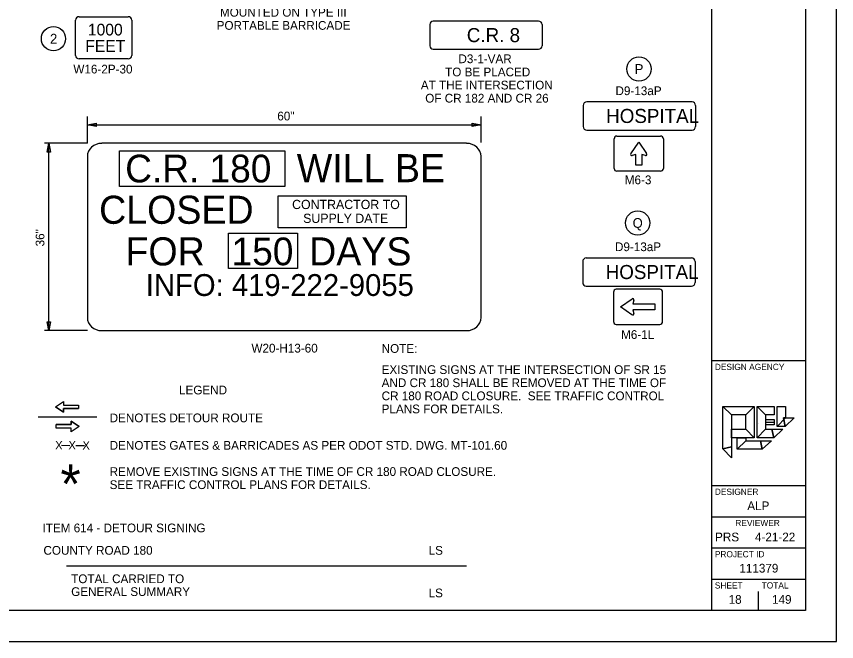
# Model space of a CAD drawing. Extents: x 1 to 1971, y -2 to 1107.
# Drawn here: x 1672.33 to 1685.46, y 1084.6 to 1094.62 of the extents above; entities that cross this region are included whole.
import ezdxf

# ---------------------------------------------------------------- set-up
doc = ezdxf.new("R2010")
doc.units = 0
for name, color, linetype in [('SH_Border', 7, 'Continuous'), ('SH_Cut_Line', 7, 'Continuous'), ('SH_Data', 7, 'Continuous'), ('SH_Text', 7, 'Continuous'), ('SN_P_Signs', 7, 'Continuous'), ('SN_P_Text', 7, 'Continuous')]:
    doc.layers.add(name, color=color, linetype=linetype)

msp = doc.modelspace()

# ---------------------------------------------------------------- linework, layer by layer
at = {"layer": 'SH_Border'}
for p, q in [((1683.463, 1085.101), (1683.463, 1106.101)), ((1683.463, 1089.101), (1684.963, 1089.101)), ((1683.463, 1087.101), (1684.963, 1087.101)), ((1683.463, 1086.601), (1684.963, 1086.601)), ((1683.463, 1086.101), (1684.963, 1086.101)), ((1683.463, 1085.601), (1684.963, 1085.601))]:
    msp.add_line(p, q, dxfattribs=at)
msp.add_lwpolyline([(1652.963, 1106.101), (1684.963, 1106.101), (1684.963, 1085.101), (1652.963, 1085.101)], close=True, dxfattribs=at)
at = {"layer": 'SH_Cut_Line'}
msp.add_lwpolyline([(1651.463, 1084.601), (1685.463, 1084.601), (1685.463, 1106.601), (1651.463, 1106.601)], close=True, dxfattribs=at)
at = {"layer": 'SH_Data'}
for p, q in [((1684.213, 1088.101), (1684.213, 1088.101)), ((1684.213, 1085.101), (1684.213, 1085.401)), ((1683.838, 1085.276), (1683.838, 1085.276))]:
    msp.add_line(p, q, dxfattribs=at)
at = {"layer": 'SH_Text'}
for p, q in [((1673.464, 1092.582), (1673.464, 1093.012)), ((1679.769, 1092.594), (1679.769, 1093.012)), ((1673.464, 1092.879), (1679.769, 1092.879)), ((1673.464, 1092.582), (1672.776, 1092.582)), ((1672.846, 1089.582), (1672.846, 1092.582)), ((1673.464, 1089.582), (1672.776, 1089.582)), ((1672.954, 1088.363), (1673.081, 1088.447)), ((1673.081, 1088.447), (1673.081, 1088.39)), ((1672.954, 1088.363), (1673.081, 1088.278)), ((1673.081, 1088.39), (1673.323, 1088.39)), ((1673.081, 1088.278), (1673.081, 1088.332)), ((1673.081, 1088.332), (1673.323, 1088.332)), ((1673.323, 1088.39), (1673.323, 1088.332)), ((1673.617, 1088.196), (1672.674, 1088.196)), ((1673.204, 1088.077), (1672.962, 1088.078)), ((1672.962, 1088.02), (1672.962, 1088.078)), ((1673.204, 1088.019), (1672.962, 1088.02)), ((1673.331, 1088.047), (1673.203, 1087.962)), ((1673.203, 1087.962), (1673.204, 1088.019)), ((1673.331, 1088.047), (1673.204, 1088.132)), ((1673.204, 1088.132), (1673.204, 1088.077)), ((1684.327, 1088.116), (1684.464, 1088.116)), ((1679.535, 1085.809), (1673.129, 1085.809))]:
    msp.add_line(p, q, dxfattribs=at)
for points in [[(1673.604, 1092.851), (1673.464, 1092.879), (1673.604, 1092.907)], [(1679.629, 1092.907), (1679.769, 1092.879), (1679.629, 1092.851)], [(1672.818, 1092.442), (1672.846, 1092.582), (1672.874, 1092.442)], [(1673.978, 1092.462), (1676.626, 1092.462), (1676.626, 1091.893), (1673.978, 1091.893)], [(1676.521, 1091.741), (1678.569, 1091.741), (1678.569, 1091.229), (1676.521, 1091.229)], [(1675.725, 1091.142), (1676.827, 1091.142), (1676.827, 1090.579), (1675.725, 1090.579)], [(1672.874, 1089.722), (1672.846, 1089.582), (1672.818, 1089.722)], [(1673.323, 1088.332), (1673.081, 1088.332), (1673.081, 1088.278), (1672.954, 1088.363), (1673.081, 1088.447), (1673.081, 1088.39), (1673.323, 1088.39)], [(1683.641, 1087.691), (1683.641, 1088.367), (1683.779, 1088.231), (1683.779, 1087.719)], [(1683.641, 1088.367), (1684.144, 1088.367), (1684.007, 1088.231), (1683.779, 1088.231)], [(1684.144, 1088.367), (1684.144, 1087.865), (1684.007, 1088.002), (1684.007, 1088.231)], [(1684.19, 1087.865), (1684.19, 1088.367), (1684.327, 1088.231), (1684.327, 1088.002)], [(1684.19, 1088.367), (1684.464, 1088.367), (1684.464, 1088.231), (1684.327, 1088.231)], [(1684.51, 1088.047), (1684.51, 1088.367), (1684.647, 1088.367), (1684.647, 1088.185)], [(1684.464, 1088.157), (1684.464, 1088.074), (1684.329, 1088.074), (1684.329, 1088.157)], [(1684.639, 1088.047), (1684.51, 1088.047), (1684.647, 1088.185), (1684.611, 1088.185)], [(1684.784, 1088.185), (1684.639, 1088.047), (1684.611, 1088.185)], [(1672.962, 1088.078), (1673.204, 1088.077), (1673.204, 1088.132), (1673.331, 1088.047), (1673.203, 1087.962), (1673.204, 1088.019), (1672.962, 1088.02)], [(1684.144, 1087.865), (1683.779, 1087.865), (1683.779, 1088.002), (1684.007, 1088.002)], [(1684.456, 1087.865), (1684.19, 1087.865), (1684.327, 1088.002), (1684.427, 1088.002)], [(1684.601, 1088.002), (1684.456, 1087.865), (1684.427, 1088.002)], [(1683.87, 1087.682), (1683.87, 1087.865), (1684.007, 1087.865), (1684.007, 1087.819)], [(1684.272, 1087.682), (1683.87, 1087.682), (1684.007, 1087.819), (1684.244, 1087.819)], [(1684.419, 1087.819), (1684.272, 1087.682), (1684.244, 1087.819)], [(1683.779, 1087.545), (1683.641, 1087.691), (1683.779, 1087.719)]]:
    msp.add_lwpolyline(points, close=True, dxfattribs=at)
for centre in [(1672.921, 1094.258), (1682.298, 1093.773), (1682.278, 1091.306)]:
    msp.add_circle(centre, 0.194, dxfattribs=at)
at = {"layer": 'SN_P_Signs'}
for p, q in [((1681.901, 1092.181), (1681.901, 1092.654)), ((1681.946, 1092.699), (1682.644, 1092.699)), ((1682.689, 1092.654), (1682.689, 1092.181)), ((1679.536, 1092.582), (1673.697, 1092.582)), ((1682.167, 1092.414), (1682.295, 1092.6)), ((1682.295, 1092.6), (1682.421, 1092.417)), ((1673.464, 1092.374), (1673.464, 1089.79)), ((1679.769, 1089.79), (1679.769, 1092.374)), ((1682.246, 1092.403), (1682.188, 1092.385)), ((1682.246, 1092.234), (1682.246, 1092.403)), ((1682.402, 1092.385), (1682.344, 1092.403)), ((1682.344, 1092.403), (1682.344, 1092.234)), ((1682.344, 1092.234), (1682.246, 1092.234)), ((1682.644, 1092.136), (1681.946, 1092.136)), ((1681.89, 1090.199), (1681.89, 1089.727)), ((1682.632, 1090.244), (1681.935, 1090.244)), ((1682.632, 1090.244), (1682.632, 1090.244)), ((1682.677, 1089.727), (1682.677, 1090.199)), ((1682.002, 1089.963), (1682.189, 1090.091)), ((1682.217, 1090.07), (1682.199, 1090.012)), ((1682.199, 1090.012), (1682.551, 1090.012)), ((1682.551, 1090.012), (1682.551, 1089.914)), ((1682.186, 1089.837), (1682.002, 1089.963)), ((1682.551, 1089.914), (1682.199, 1089.914)), ((1682.199, 1089.914), (1682.217, 1089.856)), ((1681.935, 1089.682), (1682.632, 1089.682)), ((1673.697, 1089.582), (1679.536, 1089.582)), ((1673.051, 1087.745), (1673.181, 1087.744)), ((1673.281, 1087.742), (1673.418, 1087.74))]:
    msp.add_line(p, q, dxfattribs=at)
for points in [[(1673.331, 1094.61), (1674.119, 1094.61)], [(1673.275, 1093.991), (1673.275, 1094.554)], [(1674.175, 1094.554), (1674.175, 1093.991)], [(1678.948, 1094.484), (1678.948, 1094.146)], [(1680.691, 1094.54), (1679.004, 1094.54)], [(1680.748, 1094.484), (1680.748, 1094.146)], [(1679.004, 1094.09), (1680.691, 1094.09)], [(1674.119, 1093.935), (1673.331, 1093.935)], [(1681.406, 1093.189), (1681.406, 1092.851)], [(1683.149, 1093.245), (1681.462, 1093.245)], [(1683.206, 1093.189), (1683.206, 1092.851)], [(1681.462, 1092.795), (1683.149, 1092.795)], [(1681.397, 1090.689), (1681.397, 1090.352)], [(1683.14, 1090.745), (1681.453, 1090.745)], [(1683.197, 1090.689), (1683.197, 1090.352)], [(1681.453, 1090.295), (1683.14, 1090.295)]]:
    msp.add_lwpolyline(points, dxfattribs=at)
for centre, radius, start, end in [((1673.331, 1094.554), 0.0563, 90, 180), ((1674.119, 1094.554), 0.0563, 0, 90), ((1679.004, 1094.484), 0.0563, 90, 180), ((1680.691, 1094.484), 0.0563, 0, 90), ((1679.004, 1094.146), 0.0563, 180, 270), ((1680.691, 1094.146), 0.0563, 270, 0), ((1673.331, 1093.991), 0.0563, 180, 270), ((1674.119, 1093.991), 0.0563, 270, 0), ((1681.462, 1093.189), 0.0563, 90, 180), ((1683.149, 1093.189), 0.0563, 0, 90), ((1681.462, 1092.851), 0.0563, 180, 270), ((1683.149, 1092.851), 0.0563, 270, 0), ((1681.946, 1092.654), 0.045, 90, 180), ((1682.644, 1092.654), 0.045, 0, 90), ((1682.182, 1092.403), 0.0188, 145.4112, 287.2046), ((1682.407, 1092.403), 0.0188, 252.7954, 45.0096), ((1681.946, 1092.181), 0.045, 180, 270), ((1682.644, 1092.181), 0.045, 270, 0), ((1681.453, 1090.689), 0.0563, 90, 180), ((1683.14, 1090.689), 0.0563, 0, 90), ((1681.453, 1090.352), 0.0563, 180, 270), ((1683.14, 1090.352), 0.0563, 270, 0), ((1681.935, 1090.199), 0.045, 90, 180), ((1682.632, 1090.199), 0.045, 0, 90), ((1682.199, 1090.076), 0.0188, 342.7954, 124.5888), ((1682.199, 1089.851), 0.0188, 224.9904, 17.2046), ((1681.935, 1089.727), 0.045, 180, 270), ((1682.632, 1089.727), 0.045, 270, 0)]:
    msp.add_arc(centre, radius, start, end, dxfattribs=at)
for centre, major_axis, start_param, end_param in [((1673.697, 1092.374), (-0.233, 0), 4.712389, 6.283185), ((1679.536, 1092.374), (0.233, 0), 0, 1.570796), ((1673.697, 1089.79), (-0.233, 0), 0, 1.570796), ((1679.536, 1089.79), (0.233, 0), 4.712389, 6.283185)]:
    msp.add_ellipse(centre, major_axis=major_axis, ratio=0.891693, start_param=start_param, end_param=end_param, dxfattribs=at)

# ---------------------------------------------------------------- texts
at = {"layer": 'SH_Data'}
for s, height, p in [('DESIGN AGENCY', 0.1, (1683.513, 1088.951)), ('DESIGNER', 0.1, (1683.513, 1086.951)), ('ALP', 0.14, (1684.033, 1086.706)), ('REVIEWER', 0.1, (1683.841, 1086.451)), ('PRS', 0.14, (1683.517, 1086.206)), ('4-21-22', 0.14, (1684.156, 1086.206)), ('PROJECT ID', 0.1, (1683.513, 1085.951)), ('111379', 0.14, (1683.906, 1085.706)), ('SHEET', 0.1, (1683.513, 1085.451)), ('TOTAL', 0.1, (1684.263, 1085.451)), ('18', 0.14, (1683.734, 1085.206)), ('149', 0.14, (1684.429, 1085.206))]:
    msp.add_text(s, height=height, dxfattribs=at).set_placement(p)
at = {"layer": 'SH_Text'}
for s, height, p in [('2', 0.156, (1672.866, 1094.18)), ('P', 0.156, (1682.23, 1093.695)), ('60"', 0.14, (1676.506, 1092.949)), ('C.R. 180', 0.4437, (1674.07, 1091.956)), ('WILL BE', 0.45, (1676.818, 1091.959)), ('CLOSED', 0.45, (1673.652, 1091.293)), ('CONTRACTOR TO', 0.14793, (1676.743, 1091.529)), ('SUPPLY DATE', 0.14793, (1676.92, 1091.307)), ('Q', 0.156, (1682.197, 1091.228)), ('FOR          DAYS', 0.45, (1674.074, 1090.626)), ('150', 0.4437, (1675.774, 1090.629)), ('W20-H13-60', 0.14, (1676.092, 1089.231)), ('NOTE:', 0.14, (1678.177, 1089.226)), ('EXISTING SIGNS AT THE INTERSECTION OF SR 15', 0.14, (1678.177, 1088.887)), ('AND CR 180 SHALL BE REMOVED AT THE TIME OF', 0.14, (1678.177, 1088.677)), ('LEGEND', 0.14, (1674.932, 1088.56)), ('CR 180 ROAD CLOSURE.  SEE TRAFFIC CONTROL', 0.14, (1678.177, 1088.467)), ('PLANS FOR DETAILS.', 0.14, (1678.177, 1088.257)), ('DENOTES DETOUR ROUTE', 0.14, (1673.821, 1088.114)), ('DENOTES GATES & BARRICADES AS PER ODOT STD. DWG. MT-101.60', 0.14, (1673.821, 1087.674)), ('*', 0.624, (1673.033, 1086.815)), ('REMOVE EXISTING SIGNS AT THE TIME OF CR 180 ROAD CLOSURE.', 0.14, (1673.821, 1087.254)), ('SEE TRAFFIC CONTROL PLANS FOR DETAILS.', 0.14, (1673.821, 1087.044)), ('ITEM 614 - DETOUR SIGNING', 0.14, (1672.746, 1086.351)), ('COUNTY ROAD 180', 0.14, (1672.761, 1085.992)), ('LS', 0.14, (1678.929, 1085.992)), ('TOTAL CARRIED TO', 0.14, (1673.205, 1085.537)), ('GENERAL SUMMARY', 0.14, (1673.205, 1085.331)), ('LS', 0.14, (1678.929, 1085.31))]:
    msp.add_text(s, height=height, dxfattribs=at).set_placement(p)
msp.add_text('36"', height=0.14, rotation=90, dxfattribs=at).set_placement((1672.776, 1090.931))
at = {"layer": 'SN_P_Signs'}
for s, height, p in [('1000', 0.1875, (1673.472, 1094.31)), ('C.R. 8', 0.225, (1679.541, 1094.203)), ('FEET', 0.1875, (1673.43, 1094.047)), ('HOSPITAL', 0.225, (1681.773, 1092.908)), ('HOSPITAL', 0.225, (1681.765, 1090.408)), ('INFO: 419-222-9055', 0.35, (1674.4, 1090.137))]:
    msp.add_text(s, height=height, dxfattribs=at).set_placement(p)
for p in [(1672.948, 1087.68), (1673.161, 1087.68), (1673.385, 1087.677)]:
    msp.add_text('X', height=0.133, rotation=359.2514, dxfattribs=at).set_placement(p)
at = {"layer": 'SN_P_Text'}
for s, p in [('MOUNTED ON TYPE III', (1675.588, 1094.611)), ('PORTABLE BARRICADE', (1675.535, 1094.401)), ('D3-1-VAR', (1679.407, 1093.866)), ('W16-2P-30', (1673.24, 1093.701)), ('TO BE PLACED', (1679.194, 1093.655)), ('AT THE INTERSECTION', (1678.805, 1093.445)), ('D9-13aP', (1681.922, 1093.354)), ('OF CR 182 AND CR 26', (1678.875, 1093.235)), ('M6-3', (1682.071, 1091.927)), ('D9-13aP', (1681.914, 1090.855)), ('M6-1L', (1682.012, 1089.449))]:
    msp.add_text(s, height=0.14, dxfattribs=at).set_placement(p)

doc.saveas('drawing.dxf')
